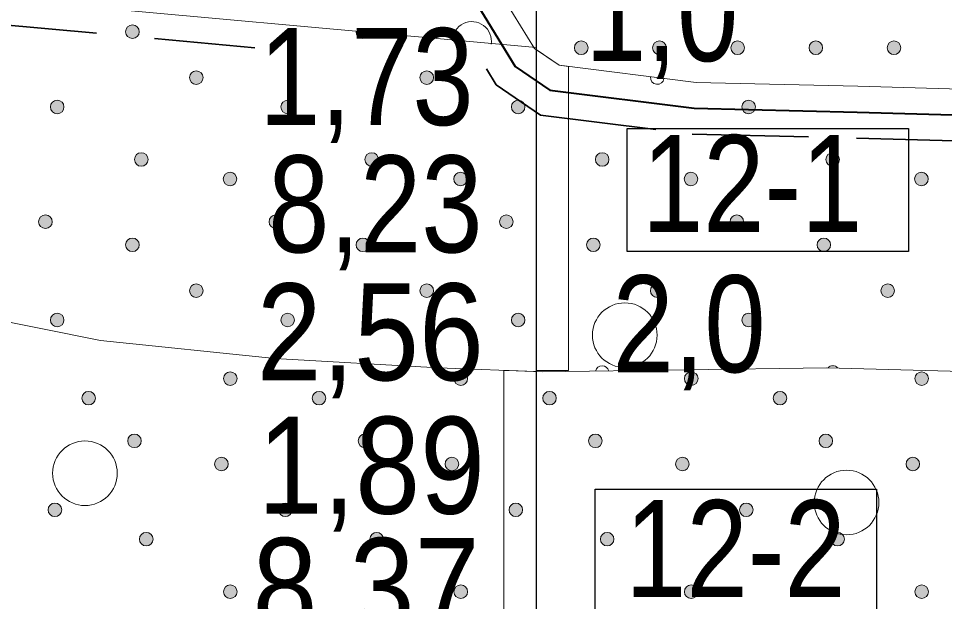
# Model space of a CAD drawing. Extents: x 640104 to 640970, y 6442278 to 6442689.
# Drawn here: x 640398.4 to 640427.06, y 6442364.3 to 6442382.35 of the extents above; entities that cross this region are included whole.
import ezdxf
from ezdxf.enums import TextEntityAlignment as Align

# ---------------------------------------------------------------- set-up
doc = ezdxf.new("R2010")
doc.units = 0
doc.header["$LTSCALE"] = 1.2
doc.linetypes.add('MEDIUM_DASHED', pattern=[4.5, 3, -1.5])
for name, color, linetype, lineweight in [('31', 7, 'Continuous', 13), ('32', 7, 'Continuous', 25), ('33', 7, 'Continuous', 13), ('35', 7, 'Continuous', 35), ('41', 7, 'Continuous', 13), ('44', 7, 'Continuous', 13), ('45', 7, 'Continuous', 13), ('47', 7, 'Continuous', 13)]:
    doc.layers.add(name, color=color, linetype=linetype, lineweight=lineweight)

msp = doc.modelspace()

# ---------------------------------------------------------------- hatches: boundary and pattern name
at = {"layer": '44'}
for points in [[(640402.132, 6442381.939, 1), (640401.712, 6442381.939, 1)], [(640404.109, 6442380.52, 1), (640403.689, 6442380.52, 1)], [(640411.242, 6442380.52, 1), (640410.822, 6442380.52, 1)], [(640399.804, 6442379.612, 1), (640399.384, 6442379.612, 1)], [(640406.937, 6442379.612, 1), (640406.517, 6442379.612, 1)], [(640414.07, 6442379.612, 1), (640413.65, 6442379.612, 1)], [(640421.203, 6442379.612, 1), (640420.783, 6442379.612, 1)], [(640402.406, 6442377.986, 1), (640401.986, 6442377.986, 1)], [(640409.539, 6442377.986, 1), (640409.119, 6442377.986, 1)], [(640416.672, 6442377.986, 1), (640416.252, 6442377.986, 1)], [(640423.805, 6442377.986, 1), (640423.385, 6442377.986, 1)], [(640405.153, 6442377.381, 1), (640404.733, 6442377.381, 1)], [(640412.286, 6442377.381, 1), (640411.866, 6442377.381, 1)], [(640419.419, 6442377.381, 1), (640418.999, 6442377.381, 1)], [(640426.552, 6442377.381, 1), (640426.132, 6442377.381, 1)], [(640399.439, 6442376.059, 1), (640399.019, 6442376.059, 1)], [(640406.572, 6442376.059, 1), (640406.152, 6442376.059, 1)], [(640413.705, 6442376.059, 1), (640413.285, 6442376.059, 1)], [(640420.838, 6442376.059, 1), (640420.418, 6442376.059, 1)], [(640402.132, 6442375.343, 1), (640401.712, 6442375.343, 1)], [(640409.265, 6442375.343, 1), (640408.845, 6442375.343, 1)], [(640416.398, 6442375.343, 1), (640415.978, 6442375.343, 1)], [(640423.531, 6442375.343, 1), (640423.111, 6442375.343, 1)], [(640404.109, 6442373.924, 1), (640403.689, 6442373.924, 1)], [(640411.242, 6442373.924, 1), (640410.822, 6442373.924, 1)], [(640418.375, 6442373.924, 1), (640417.955, 6442373.924, 1)], [(640425.508, 6442373.924, 1), (640425.088, 6442373.924, 1)], [(640399.804, 6442373.016, 1), (640399.384, 6442373.016, 1)], [(640406.937, 6442373.016, 1), (640406.517, 6442373.016, 1)], [(640414.07, 6442373.016, 1), (640413.65, 6442373.016, 1)], [(640421.203, 6442373.016, 1), (640420.783, 6442373.016, 1)], [(640405.161, 6442371.202, 1), (640404.741, 6442371.202, 1)], [(640412.294, 6442371.202, 1), (640411.874, 6442371.202, 1)], [(640419.427, 6442371.202, 1), (640419.007, 6442371.202, 1)], [(640426.56, 6442371.202, 1), (640426.14, 6442371.202, 1)], [(640400.776, 6442370.597, 1), (640400.356, 6442370.597, 1)], [(640407.909, 6442370.597, 1), (640407.489, 6442370.597, 1)], [(640415.042, 6442370.597, 1), (640414.622, 6442370.597, 1)], [(640422.175, 6442370.597, 1), (640421.755, 6442370.597, 1)], [(640402.195, 6442369.275, 1), (640401.775, 6442369.275, 1)], [(640409.328, 6442369.275, 1), (640408.908, 6442369.275, 1)], [(640416.461, 6442369.275, 1), (640416.041, 6442369.275, 1)], [(640423.594, 6442369.275, 1), (640423.174, 6442369.275, 1)], [(640404.887, 6442368.559, 1), (640404.467, 6442368.559, 1)], [(640412.02, 6442368.559, 1), (640411.6, 6442368.559, 1)], [(640419.153, 6442368.559, 1), (640418.733, 6442368.559, 1)], [(640426.286, 6442368.559, 1), (640425.866, 6442368.559, 1)], [(640399.732, 6442367.14, 1), (640399.312, 6442367.14, 1)], [(640406.865, 6442367.14, 1), (640406.445, 6442367.14, 1)], [(640413.998, 6442367.14, 1), (640413.578, 6442367.14, 1)], [(640421.131, 6442367.14, 1), (640420.711, 6442367.14, 1)], [(640402.559, 6442366.232, 1), (640402.139, 6442366.232, 1)], [(640409.692, 6442366.232, 1), (640409.272, 6442366.232, 1)], [(640416.825, 6442366.232, 1), (640416.405, 6442366.232, 1)], [(640423.958, 6442366.232, 1), (640423.538, 6442366.232, 1)], [(640405.161, 6442364.606, 1), (640404.741, 6442364.606, 1)], [(640412.294, 6442364.606, 1), (640411.874, 6442364.606, 1)], [(640419.427, 6442364.606, 1), (640419.007, 6442364.606, 1)], [(640426.56, 6442364.606, 1), (640426.14, 6442364.606, 1)]]:
    msp.add_hatch(color=256, dxfattribs=at).paths.add_polyline_path(points)
at = {"layer": '45'}
for points in [[(640416.023, 6442381.443, 1), (640415.603, 6442381.443, 1)], [(640418.443, 6442381.443, 1), (640418.023, 6442381.443, 1)], [(640420.863, 6442381.443, 1), (640420.443, 6442381.443, 1)], [(640423.283, 6442381.443, 1), (640422.863, 6442381.443, 1)], [(640425.703, 6442381.443, 1), (640425.283, 6442381.443, 1)]]:
    msp.add_hatch(color=256, dxfattribs=at).paths.add_polyline_path(points)

# ---------------------------------------------------------------- linework, layer by layer
at = {"layer": '31'}
for points in [[(640139.08, 6442423.82), (640151.96, 6442423.75), (640173.66, 6442421.26), (640213.16, 6442416.61), (640233.94, 6442414.53), (640242.79, 6442413.66), (640295.17, 6442389.83), (640328.15, 6442387.74), (640358.78, 6442385.66), (640377.96, 6442384.87), (640391.41, 6442383.72), (640397.31, 6442383.01), (640414.42, 6442381.45)], [(640406.72, 6442397.88), (640407.72, 6442395.6), (640408.48, 6442393.55), (640409.45, 6442391.23), (640410.13, 6442389.25), (640411.66, 6442386.01), (640413.07, 6442383.54), (640414.37, 6442381.42), (640415.13, 6442380.9), (640419.37, 6442380.37), (640424.37, 6442380.25), (640433.96, 6442379.98), (640441.04, 6442380.03), (640448.6, 6442379.6), (640453.66, 6442379.25), (640461.37, 6442378.83)], [(640368.92, 6442385.24), (640371.57, 6442384.43), (640374.23, 6442383.31), (640378.94, 6442380.49), (640385.79, 6442376.51), (640388.32, 6442375.25), (640390.29, 6442374.75), (640393.64, 6442373.85), (640400.93, 6442372.38), (640406.33, 6442371.82), (640411.39, 6442371.54), (640414.6, 6442371.41), (640423.41, 6442371.54), (640447.85, 6442370.88), (640460.41, 6442370.88), (640471.22, 6442370.34), (640473.77, 6442369.96)]]:
    msp.add_lwpolyline(points, dxfattribs=at)
at = {"layer": '32'}
msp.add_line((640414.42, 6442391.45), (640414.42, 6442344.45), dxfattribs=at)
at = {"layer": '33'}
for points in [[(640415.42, 6442371.45), (640415.42, 6442380.86), (640415.13, 6442380.9), (640414.42, 6442381.39), (640414.42, 6442371.45), (640414.6, 6442371.45)], [(640413.42, 6442371.45), (640413.42, 6442361.45), (640414.42, 6442361.45), (640414.42, 6442371.42), (640414.41, 6442371.42), (640413.58, 6442371.45)]]:
    msp.add_lwpolyline(points, close=True, dxfattribs=at)
at = {"layer": '33', "lineweight": 25}
for points in [[(640417.23, 6442378.94), (640425.94, 6442378.94), (640425.94, 6442375.14), (640417.23, 6442375.14)], [(640416.24, 6442367.78), (640424.95, 6442367.78), (640424.95, 6442363.98), (640416.24, 6442363.98)]]:
    msp.add_lwpolyline(points, close=True, dxfattribs=at)
at = {"layer": '35', "linetype": 'MEDIUM_DASHED'}
for points in [[(640153.52, 6442422.77), (640173.56, 6442420.47), (640213.07, 6442415.82), (640233.86, 6442413.74), (640242.58, 6442412.88), (640294.97, 6442389.04), (640328.09, 6442386.94), (640358.73, 6442384.86), (640377.91, 6442384.07), (640391.32, 6442382.92), (640397.23, 6442382.22), (640405.71, 6442381.44)], [(640412.88, 6442380.79), (640413.18, 6442380.3), (640414.55, 6442379.36), (640419.25, 6442378.77), (640424.33, 6442378.65), (640433.95, 6442378.38), (640441, 6442378.43), (640448.5, 6442378), (640453.56, 6442377.65), (640461.01, 6442377.24)]]:
    msp.add_lwpolyline(points, dxfattribs=at)
at = {"layer": '35', "lineweight": 40}
msp.add_lwpolyline([(640406.16, 6442397.5), (640407.74, 6442393.26), (640408.7, 6442390.95), (640409.39, 6442388.95), (640410.95, 6442385.64), (640412.39, 6442383.13), (640413.77, 6442380.86), (640414.84, 6442380.13), (640419.31, 6442379.57), (640424.35, 6442379.45), (640433.96, 6442379.18), (640441.02, 6442379.23), (640448.55, 6442378.8), (640453.61, 6442378.45), (640461.31, 6442378.03)], dxfattribs=at)
at = {"layer": '41'}
for centre, radius, start, end in [((640412.431, 6442381.652), 0.6, 350.2471, 179.1147), ((640410.045, 6442381.649), 0.3, 31.0252, 138.3366)]:
    msp.add_arc(centre, radius, start, end, dxfattribs=at)
at = {"layer": '44'}
for centre in [(640401.922, 6442381.939), (640403.899, 6442380.52), (640411.032, 6442380.52), (640399.594, 6442379.612), (640406.727, 6442379.612), (640413.86, 6442379.612), (640420.993, 6442379.612), (640402.196, 6442377.986), (640409.329, 6442377.986), (640416.462, 6442377.986), (640423.595, 6442377.986), (640404.943, 6442377.381), (640412.076, 6442377.381), (640419.209, 6442377.381), (640426.342, 6442377.381), (640399.229, 6442376.059), (640406.362, 6442376.059), (640413.495, 6442376.059), (640420.628, 6442376.059), (640401.922, 6442375.343), (640409.055, 6442375.343), (640416.188, 6442375.343), (640423.321, 6442375.343), (640403.899, 6442373.924), (640411.032, 6442373.924), (640418.165, 6442373.924), (640425.298, 6442373.924), (640399.594, 6442373.016), (640406.727, 6442373.016), (640413.86, 6442373.016), (640420.993, 6442373.016), (640404.951, 6442371.202), (640412.084, 6442371.202), (640419.217, 6442371.202), (640426.35, 6442371.202), (640400.566, 6442370.597), (640407.699, 6442370.597), (640414.832, 6442370.597), (640421.965, 6442370.597), (640401.985, 6442369.275), (640409.118, 6442369.275), (640416.251, 6442369.275), (640423.384, 6442369.275), (640404.677, 6442368.559), (640411.81, 6442368.559), (640418.943, 6442368.559), (640426.076, 6442368.559), (640399.522, 6442367.14), (640406.655, 6442367.14), (640413.788, 6442367.14), (640420.921, 6442367.14), (640402.349, 6442366.232), (640409.482, 6442366.232), (640416.615, 6442366.232), (640423.748, 6442366.232), (640404.951, 6442364.606), (640412.084, 6442364.606), (640419.217, 6442364.606), (640426.35, 6442364.606)]:
    msp.add_circle(centre, 0.21, dxfattribs=at)
for centre, start, end in [((640409.055, 6442381.939), 179.9811, 349.3807), ((640418.165, 6442380.52), 173.956, 351.794), ((640416.462, 6442371.39), 14.4271, 167.309), ((640423.595, 6442371.39), 43.8398, 133.0301)]:
    msp.add_arc(centre, 0.21, start, end, dxfattribs=at)
at = {"layer": '45'}
for centre in [(640415.813, 6442381.443), (640418.233, 6442381.443), (640420.653, 6442381.443), (640423.073, 6442381.443), (640425.493, 6442381.443)]:
    msp.add_circle(centre, 0.21, dxfattribs=at)
at = {"layer": '47'}
for centre in [(640417.16, 6442372.547), (640400.453, 6442368.274), (640424.024, 6442367.367)]:
    msp.add_circle(centre, 1, dxfattribs=at)

# ---------------------------------------------------------------- texts
at = {"layer": '32', "width": 0.85}
for s, p in [('1,0', (640418.305, 6442381.03)), ('2,0', (640419.15, 6442371.4))]:
    msp.add_text(s, height=3, dxfattribs=at).set_placement(p, align=Align.CENTER)
at = {"layer": '33'}
for s, width, p in [('1,73', 0.85, (640409.165, 6442379.05)), ('12-1', 0.85, (640421.105, 6442375.74)), ('8,23', 0.85, (640409.44, 6442375.11)), ('2,56', 0.9, (640409.285, 6442371.15)), ('1,89', 0.9, (640409.32, 6442367.02)), ('12-2', 0.85, (640420.585, 6442364.44)), ('8,37', 0.9, (640409.15, 6442363.27))]:
    msp.add_text(s, height=3, dxfattribs=dict(at, width=width)).set_placement(p, align=Align.CENTER)

doc.saveas('drawing.dxf')
